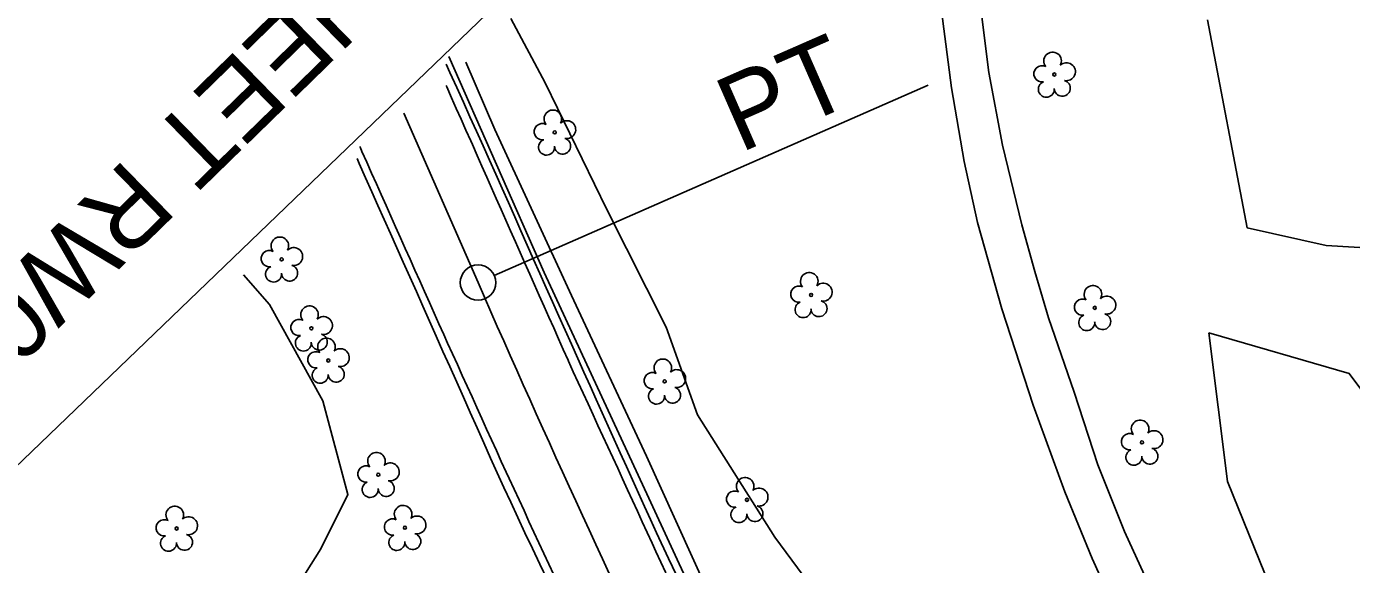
# Model space of a CAD drawing. Extents: x 474972 to 479313, y 498315 to 502691.
# Drawn here: x 475891.1 to 476171.4, y 501612 to 501725.9 of the extents above; entities that cross this region are included whole.
import ezdxf

# ---------------------------------------------------------------- set-up
doc = ezdxf.new("R2010")
doc.units = 0
for name, color, linetype in [('Exist Guardrail', 7, 'Continuous'), ('Exist Horizontal Alignment', 7, 'Continuous'), ('Exist Roads EOP', 7, 'Continuous'), ('Exist Roads EOT', 7, 'Continuous'), ('Exist Roads Soil', 7, 'Continuous'), ('Exist Vegetation Hedge Row', 7, 'Continuous'), ('Exist Vegetation Tree CELL', 7, 'Continuous'), ('Exist Vegetation Woods Line', 7, 'Continuous'), ('Matchline', 7, 'Continuous'), ('Matchline Text', 7, 'Continuous')]:
    doc.layers.add(name, color=color, linetype=linetype)

msp = doc.modelspace()

# ---------------------------------------------------------------- linework, layer by layer
at = {"layer": 'Exist Guardrail'}
for points in [[(475980.43, 501719.52), (476000.62, 501673.83), (476022.76, 501626.04)], [(476022.76, 501626.04), (476031.8, 501606.5), (476046.22, 501576.76), (476066.08, 501535.85), (476079.91, 501508.65), (476098.09, 501472.91), (476116.59, 501438.31), (476140.29, 501395.78), (476158.27, 501364.42), (476168.54, 501347.18), (476182.34, 501324.79), (476193.05, 501307.85), (476195.59, 501304.15)]]:
    msp.add_lwpolyline(points, dxfattribs=at)
at = {"layer": 'Exist Horizontal Alignment'}
for p, q in [((475990.06, 501673.2), (476081.87, 501713.45)), ((475986.62, 501671.69), (475970.9, 501707.55))]:
    msp.add_line(p, q, dxfattribs=at)
msp.add_circle((475986.62, 501671.69), 3.75, dxfattribs=at)
msp.add_arc((478949.91, 502971.03), 3235.64, 203.67637, 207.50231, dxfattribs=at)
at = {"layer": 'Exist Roads EOP'}
for points in [[(475979.87, 501717.91), (475980.68, 501716.12), (475982.11, 501712.97), (475983.52, 501709.86), (475984.92, 501706.77), (475986.31, 501703.71), (475987.68, 501700.66), (475989.04, 501697.63), (475990.38, 501694.62), (475991.71, 501691.61), (475993.05, 501688.61), (475994.38, 501685.61), (475995.71, 501682.61), (475997.05, 501679.61), (475998.38, 501676.61), (475999.71, 501673.61), (476001.05, 501670.61), (476002.38, 501667.61), (476003.71, 501664.61), (476005.05, 501661.62), (476006.38, 501658.63), (476007.71, 501655.66), (476009.02, 501652.73), (476010.32, 501649.83), (476011.59, 501646.98), (476012.86, 501644.14), (476014.14, 501641.31), (476015.43, 501638.47), (476016.72, 501635.64), (476018.01, 501632.8), (476019.3, 501629.97), (476020.58, 501627.15), (476021.87, 501624.33), (476023.14, 501621.53), (476024.42, 501618.76), (476026.95, 501613.33), (476029.47, 501608.01)], [(476001.31, 501608.73), (475999.73, 501612.07), (475998.13, 501615.42), (475996.55, 501618.74), (475995.02, 501621.99), (475993.53, 501625.19), (475992.1, 501628.32), (475990.68, 501631.43), (475989.27, 501634.57), (475987.84, 501637.75), (475986.42, 501640.96), (475984.99, 501644.18), (475983.55, 501647.41), (475982.11, 501650.65), (475980.66, 501653.9), (475979.21, 501657.13), (475977.78, 501660.34), (475976.36, 501663.52), (475974.96, 501666.68), (475973.57, 501669.82), (475972.18, 501672.92), (475970.8, 501676), (475969.43, 501679.05), (475968.08, 501682.07), (475966.74, 501685.06), (475965.43, 501688.01), (475964.14, 501690.92), (475962.84, 501693.87), (475961.49, 501696.92), (475961.04, 501697.95)]]:
    msp.add_lwpolyline(points, dxfattribs=at)
at = {"layer": 'Exist Roads EOT'}
for points in [[(476026.39, 501610.29), (476025.33, 501612.55), (476024.27, 501614.81), (476023.47, 501616.52), (476022.42, 501618.79), (476021.38, 501621.05), (476020.34, 501623.32), (476019.29, 501625.59), (476018.25, 501627.86), (476017.21, 501630.13), (476016.17, 501632.4), (476015.12, 501634.67), (476014.08, 501636.93), (476013.04, 501639.2), (476012, 501641.47), (476010.95, 501643.74), (476009.91, 501646.01), (476008.87, 501648.28), (476007.82, 501650.54), (476006.78, 501652.81), (476005.74, 501655.08), (476005.67, 501655.24), (476004.65, 501657.52), (476003.64, 501659.8), (476002.63, 501662.09), (476001.62, 501664.37), (476000.61, 501666.65), (475999.59, 501668.93), (475998.58, 501671.21), (475997.57, 501673.5), (475996.56, 501675.78), (475995.55, 501678.06), (475994.53, 501680.34), (475993.52, 501682.62), (475992.51, 501684.91), (475991.5, 501687.19), (475990.49, 501689.47), (475989.47, 501691.75), (475988.46, 501694.03), (475987.45, 501696.32), (475986.44, 501698.6), (475985.43, 501700.88), (475985.07, 501701.68), (475984.06, 501703.96), (475983.05, 501706.24), (475982.03, 501708.53), (475981.02, 501710.81), (475980.01, 501713.09), (475979.87, 501713.42)], [(476002.64, 501609.83), (476001.59, 501612.09), (476000.54, 501614.36), (475999.49, 501616.63), (475998.44, 501618.89), (475997.4, 501621.16), (475996.35, 501623.43), (475995.3, 501625.69), (475994.25, 501627.96), (475993.2, 501630.23), (475992.58, 501631.59), (475991.54, 501633.86), (475990.51, 501636.13), (475989.48, 501638.41), (475988.45, 501640.68), (475987.42, 501642.96), (475986.39, 501645.23), (475985.35, 501647.51), (475984.32, 501649.78), (475983.29, 501652.05), (475982.26, 501654.33), (475981.23, 501656.6), (475980.19, 501658.88), (475979.38, 501660.68), (475978.36, 501662.95), (475977.34, 501665.23), (475976.32, 501667.51), (475975.3, 501669.79), (475974.29, 501672.07), (475973.27, 501674.35), (475972.25, 501676.63), (475971.23, 501678.91), (475970.21, 501681.19), (475969.19, 501683.47), (475968.18, 501685.75), (475967.16, 501688.03), (475966.14, 501690.31), (475965.12, 501692.59), (475964.1, 501694.87), (475963.08, 501697.15), (475962.06, 501699.43), (475961.73, 501700.19), (475961.6, 501700.47)]]:
    msp.add_lwpolyline(points, dxfattribs=at)
at = {"layer": 'Exist Roads Soil'}
for points in [[(476083.55, 501814.82), (476083.56, 501814.7), (476084.8, 501799.24), (476086.08, 501784.87), (476087.92, 501770.74), (476089.49, 501757.5), (476090.7, 501745.66), (476093, 501729.64), (476094.73, 501716.14), (476097.61, 501700.79), (476101.69, 501683.88)], [(476092.31, 501684.44), (476089.46, 501697.28), (476086.83, 501712.92), (476084.68, 501729.2), (476082.47, 501748.93), (476080.42, 501764.36), (476078.47, 501778.7), (476076.9, 501793.78), (476075.65, 501808.08)], [(476092.31, 501684.44), (476097.49, 501666.15), (476104.11, 501645.78), (476110.79, 501627.44), (476116.58, 501613.33), (476122.33, 501600.52), (476126.42, 501592.47), (476133.29, 501578.92), (476139.92, 501566.08), (476145.14, 501556.45), (476151.68, 501545.35), (476159.53, 501533.17), (476169.63, 501518.27), (476173.89, 501511.76), (476178.53, 501503.54), (476182.54, 501493.47), (476185.63, 501482.9), (476188.11, 501472.97), (476191.26, 501459.13), (476193.58, 501451.58), (476195.17, 501443.4), (476197.02, 501430.55)], [(476206.49, 501429.83), (476203.88, 501443.85), (476200.39, 501459.45), (476197.32, 501472.03), (476193.41, 501486.94), (476188.94, 501498.73), (476184.06, 501510.59), (476179.74, 501519.03), (476175.46, 501526.57), (476170.98, 501533.23), (476166.32, 501539.96), (476161.09, 501547.83), (476155.13, 501557.14), (476147.73, 501569.35), (476141.92, 501580.63), (476135.99, 501592.05), (476129.23, 501606.36), (476123.44, 501618.99), (476117.8, 501633.09), (476112.76, 501648.47), (476107.35, 501664.22), (476104.43, 501674.03), (476101.69, 501683.88)]]:
    msp.add_lwpolyline(points, dxfattribs=at)
at = {"layer": 'Exist Vegetation Hedge Row'}
for points in [[(475993.54, 501727.54), (476000.81, 501713.95), (476013.85, 501687.14), (476026.43, 501662.24), (476033.03, 501643.73)], [(476022.28, 501634.99), (476006.38, 501668.99), (475990.19, 501704.12), (475984.04, 501718.34)], [(475937, 501673.32), (475942.49, 501667.07), (475953.78, 501646.64), (475959.09, 501626.85), (475953.34, 501615.33), (475946.85, 501605.05), (475938.56, 501588.38), (475932.17, 501573.55)], [(476033.03, 501643.73), (476049.4, 501617.8), (476075.8, 501582.16), (476069.78, 501577.16), (476089.5, 501541.45), (476077.82, 501534.89), (476066.33, 501550.81), (476050.08, 501576.88), (476035.07, 501606.82), (476022.28, 501634.99)]]:
    msp.add_lwpolyline(points, dxfattribs=at)
at = {"layer": 'Exist Vegetation Tree CELL'}
for p, q in [((476108.57, 501715.72), (476108.57, 501715.72)), ((476002.84, 501703.47), (476002.84, 501703.47)), ((475945.07, 501676.6), (475945.07, 501676.6)), ((476057.1, 501669.08), (476057.1, 501669.08)), ((476117.12, 501666.34), (476117.12, 501666.34)), ((475951.36, 501662.01), (475951.36, 501662.01)), ((475954.93, 501655.21), (475954.93, 501655.21)), ((476026.11, 501650.78), (476026.11, 501650.78)), ((476127.1, 501637.87), (476127.1, 501637.87)), ((475965.52, 501631.03), (475965.52, 501631.03)), ((476043.53, 501625.71), (476043.53, 501625.71)), ((475971.15, 501619.81), (475971.15, 501619.81)), ((475922.84, 501619.65), (475922.84, 501619.65))]:
    msp.add_line(p, q, dxfattribs=at)
for centre in [(476108.57, 501715.72), (476002.84, 501703.47), (475945.07, 501676.6), (476057.1, 501669.08), (476117.12, 501666.34), (475951.36, 501662.01), (475954.93, 501655.21), (476026.11, 501650.78), (476127.1, 501637.87), (475965.52, 501631.03), (476043.53, 501625.71), (475922.84, 501619.65), (475971.15, 501619.81)]:
    msp.add_circle(centre, 0.326, dxfattribs=at)
for centre, radius, start, end in [((476108.19, 501718.59), 1.86, 330.1651, 219.7134), ((476111.12, 501716.31), 1.9, 257.1011, 134.1999), ((476105.97, 501715.87), 1.73, 62.6636, 279.3457), ((476106.87, 501712.6), 1.69, 111.5671, 6.231), ((476110.24, 501712.82), 1.7, 181.2822, 74.56), ((476002.45, 501706.35), 1.86, 330.1651, 219.7134), ((476000.23, 501703.63), 1.73, 62.6636, 279.3457), ((476005.39, 501704.06), 1.9, 257.1011, 134.1999), ((476001.13, 501700.35), 1.69, 111.5671, 6.231), ((476004.51, 501700.57), 1.7, 181.2822, 74.56), ((475944.69, 501679.48), 1.86, 330.1651, 219.7134), ((475947.62, 501677.19), 1.9, 257.1011, 134.1999), ((475942.47, 501676.76), 1.73, 62.6636, 279.3457), ((475943.37, 501673.48), 1.69, 111.5671, 6.231), ((475946.75, 501673.71), 1.7, 181.2822, 74.56), ((476056.71, 501671.96), 1.86, 330.1651, 219.7134), ((476054.49, 501669.24), 1.73, 62.6636, 279.3457), ((476059.65, 501669.67), 1.9, 257.1011, 134.1999), ((476116.74, 501669.21), 1.86, 330.1651, 219.7134), ((476055.4, 501665.96), 1.69, 111.5671, 6.231), ((476058.77, 501666.18), 1.7, 181.2822, 74.56), ((476114.52, 501666.49), 1.73, 62.6636, 279.3457), ((476119.67, 501666.93), 1.9, 257.1011, 134.1999), ((475950.97, 501664.89), 1.86, 330.1651, 219.7134), ((476115.42, 501663.22), 1.69, 111.5671, 6.231), ((476118.79, 501663.44), 1.7, 181.2822, 74.56), ((475948.75, 501662.17), 1.73, 62.6636, 279.3457), ((475953.91, 501662.6), 1.9, 257.1011, 134.1999), ((475949.66, 501658.89), 1.69, 111.5671, 6.231), ((475953.03, 501659.11), 1.7, 181.2822, 74.56), ((475954.55, 501658.08), 1.86, 330.1651, 219.7134), ((475952.33, 501655.36), 1.73, 62.6636, 279.3457), ((475957.48, 501655.8), 1.9, 257.1011, 134.1999), ((475953.23, 501652.09), 1.69, 111.5671, 6.231), ((475956.61, 501652.31), 1.7, 181.2822, 74.56), ((476025.72, 501653.66), 1.86, 330.1651, 219.7134), ((476023.5, 501650.94), 1.73, 62.6636, 279.3457), ((476028.66, 501651.37), 1.9, 257.1011, 134.1999), ((476024.4, 501647.66), 1.69, 111.5671, 6.231), ((476027.78, 501647.88), 1.7, 181.2822, 74.56), ((476126.71, 501640.74), 1.86, 330.1651, 219.7134), ((476124.49, 501638.02), 1.73, 62.6636, 279.3457), ((476129.65, 501638.45), 1.9, 257.1011, 134.1999), ((475965.13, 501633.9), 1.86, 330.1651, 219.7134), ((476125.39, 501634.74), 1.69, 111.5671, 6.231), ((476128.77, 501634.97), 1.7, 181.2822, 74.56), ((475962.91, 501631.18), 1.73, 62.6636, 279.3457), ((475968.06, 501631.62), 1.9, 257.1011, 134.1999), ((475963.81, 501627.91), 1.69, 111.5671, 6.231), ((475967.19, 501628.13), 1.7, 181.2822, 74.56), ((476043.14, 501628.59), 1.86, 330.1651, 219.7134), ((476040.92, 501625.87), 1.73, 62.6636, 279.3457), ((476046.08, 501626.3), 1.9, 257.1011, 134.1999), ((475922.45, 501622.52), 1.86, 330.1651, 219.7134), ((475970.76, 501622.69), 1.86, 330.1651, 219.7134), ((476041.83, 501622.59), 1.69, 111.5671, 6.231), ((476045.2, 501622.81), 1.7, 181.2822, 74.56), ((475920.23, 501619.8), 1.73, 62.6636, 279.3457), ((475925.38, 501620.24), 1.9, 257.1011, 134.1999), ((475968.54, 501619.97), 1.73, 62.6636, 279.3457), ((475973.7, 501620.4), 1.9, 257.1011, 134.1999), ((475921.13, 501616.53), 1.69, 111.5671, 6.231), ((475924.51, 501616.75), 1.7, 181.2822, 74.56), ((475969.44, 501616.69), 1.69, 111.5671, 6.231), ((475972.82, 501616.91), 1.7, 181.2822, 74.56)]:
    msp.add_arc(centre, radius, start, end, dxfattribs=at)
at = {"layer": 'Exist Vegetation Woods Line'}
for points in [[(476187.79, 501751.97), (476187.19, 501730.04), (476202.62, 501717.27), (476190.92, 501678.08), (476166.08, 501679.55), (476149.37, 501683.26), (476140.99, 501727.29)], [(476141.27, 501661.03), (476170.98, 501652.43), (476193.29, 501622.56), (476219.36, 501537.22), (476233.52, 501505.87), (476224.61, 501499.47), (476199.55, 501526.39), (476162.21, 501587.65), (476145.18, 501629.63), (476141.27, 501661.03)]]:
    msp.add_lwpolyline(points, dxfattribs=at)
at = {"layer": 'Matchline'}
msp.add_line((475766.52, 501515.03), (476126.81, 501861.72), dxfattribs=at)

# ---------------------------------------------------------------- texts
at = {"layer": 'Exist Horizontal Alignment'}
msp.add_text('PT', height=16, rotation=23.6764, dxfattribs=at).set_placement((476042.04, 501699.04))
at = {"layer": 'Matchline Text'}
msp.add_text('MATCHLINE SHEET RW02C-6', height=16, rotation=224.2987, dxfattribs=at).set_placement((476060.16, 501842.71))

doc.saveas('drawing.dxf')
